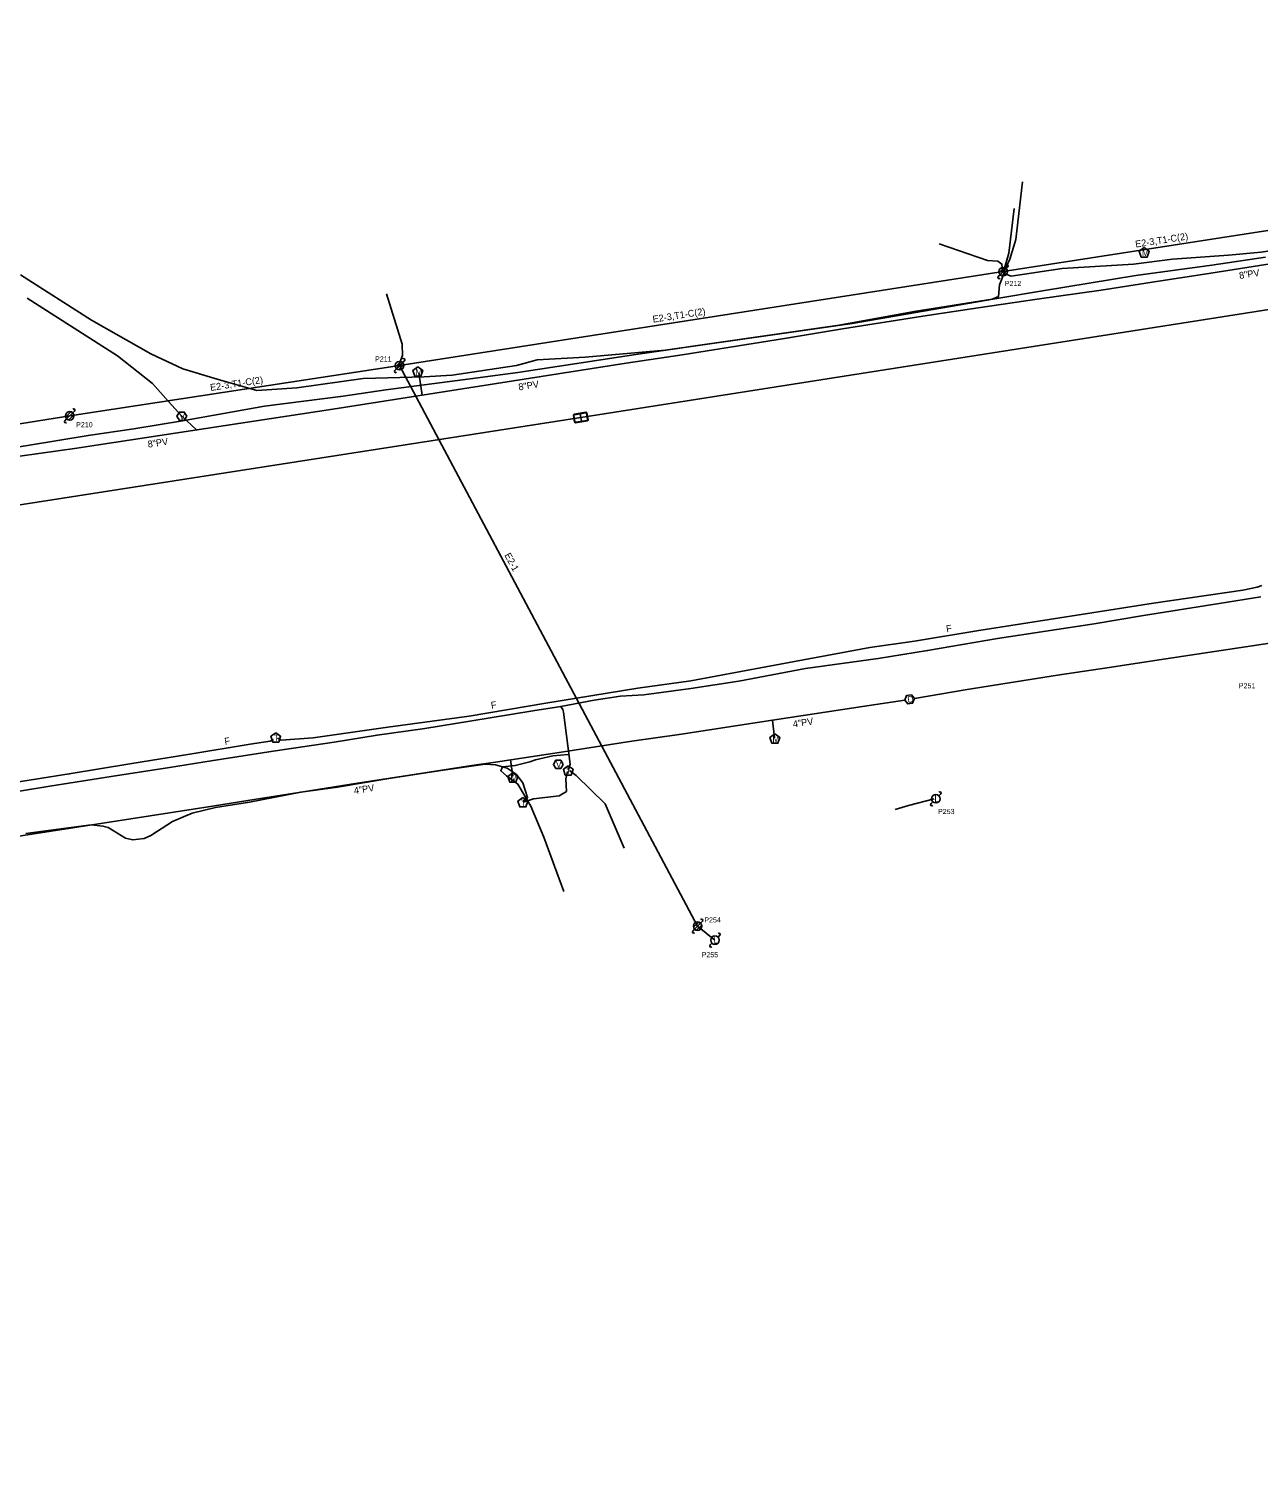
# Model space of a CAD drawing. Extents: x 1614474 to 1865144, y 1098877 to 1212550.
# Drawn here: x 1774346 to 1775065, y 1179234 to 1180084 of the extents above; entities that cross this region are included whole.
import ezdxf

# ---------------------------------------------------------------- set-up
doc = ezdxf.new("R2010")
doc.units = 0
for name, color, linetype in [('BFUSER_DUCTENCLOSURE', 7, 'Continuous'), ('BFUSER_FIBERSPAN', 7, 'Continuous'), ('RD_EX_SU_Elec', 7, 'Continuous'), ('RD_EX_SU_H2O', 7, 'Continuous'), ('RD_EX_SU_Ovhd', 7, 'Continuous'), ('RD_EX_SU_Pole', 7, 'Continuous'), ('RD_EX_SU_Telecom', 7, 'Continuous'), ('RD_EX_SU_TX_H2O', 7, 'Continuous'), ('RD_EX_SU_TX_Pole', 7, 'Continuous'), ('RD_EX_SU_TX_Telecom', 7, 'Continuous')]:
    doc.layers.add(name, color=color, linetype=linetype)

# ---------------------------------------------------------------- blocks, each defined once
blk = doc.blocks.new('SUE_WV')
at = {"layer": 'RD_EX_SU_H2O'}
blk.add_lwpolyline([(2.89, 0), (1.44, 2.5), (-1.44, 2.5), (-2.89, 0), (-1.44, -2.5), (1.44, -2.5)], close=True, dxfattribs=at)
blk.add_text('V', height=3.75, dxfattribs=at).set_placement((-1.43, -1.88))
blk = doc.blocks.new('SUE_TPP')
at = {"layer": 'RD_EX_SU_Telecom'}
blk.add_lwpolyline([(0, 3), (-2.85, 0.93), (-1.76, -2.43), (1.76, -2.43), (2.85, 0.93)], close=True, dxfattribs=at)
blk.add_text('T', height=3.75, dxfattribs=at).set_placement((-1.25, -1.88))
blk = doc.blocks.new('SUE_WM')
at = {"layer": 'RD_EX_SU_H2O'}
blk.add_lwpolyline([(0, 3.05), (-2.9, 0.94), (-1.79, -2.47), (1.79, -2.47), (2.9, 0.94)], close=True, dxfattribs=at)
blk.add_text('M', height=3.75, dxfattribs=at).set_placement((-1.43, -1.88))

msp = doc.modelspace()

# ---------------------------------------------------------------- linework, layer by layer
at = {"layer": 'BFUSER_DUCTENCLOSURE'}
msp.add_line((1774668.33, 1179858.97), (1774669.09, 1179854.53), dxfattribs=at)
for points in [[(1774665.1, 1179854.11), (1774664.43, 1179858.05)], [(1774665.31, 1179854.29), (1774664.68, 1179857.94)], [(1774664.84, 1179858.63), (1774671.74, 1179859.81)], [(1774665.01, 1179858.41), (1774671.65, 1179859.54)], [(1774672.58, 1179854.88), (1774665.68, 1179853.7)], [(1774665.77, 1179853.96), (1774672.41, 1179855.1)], [(1774672.11, 1179859.22), (1774672.73, 1179855.56)], [(1774672.31, 1179859.4), (1774672.99, 1179855.46)]]:
    msp.add_lwpolyline(points, dxfattribs=at)
for centre, radius, start, end in [((1774664.92, 1179858.13), 0.5, 99.71434, 189.71434), ((1774665.08, 1179858.01), 0.4, 99.71434, 189.71434), ((1774665.7, 1179854.36), 0.4, 189.71434, 279.71434), ((1774671.72, 1179859.15), 0.4, 9.71434, 99.71434), ((1774671.82, 1179859.31), 0.5, 9.71434, 99.71434), ((1774672.34, 1179855.49), 0.4, 279.71434, 9.71434), ((1774672.5, 1179855.37), 0.5, 279.71434, 9.71434), ((1774665.6, 1179854.19), 0.5, 189.71434, 279.71434)]:
    msp.add_arc(centre, radius, start, end, dxfattribs=at)
at = {"layer": 'BFUSER_FIBERSPAN'}
msp.add_lwpolyline([(1772266.13, 1179233.73), (1772993.33, 1179552.36), (1773074.83, 1179562.18), (1773346.25, 1179631.55), (1773610.67, 1179692.14), (1774668.73, 1179856.77), (1776115.67, 1180083.91)], dxfattribs=at)
at = {"layer": 'RD_EX_SU_Elec'}
for points in [[(1774916.25, 1179942.7), (1774919.1, 1179952.84), (1774922.26, 1179978.94)], [(1774555.08, 1179929.09), (1774564.29, 1179899.72), (1774564.41, 1179893.09), (1774561.67, 1179885.87)], [(1774852.52, 1179627.55), (1774860.33, 1179629.86), (1774875.4, 1179633.84)]]:
    msp.add_lwpolyline(points, dxfattribs=at)
at = {"layer": 'RD_EX_SU_H2O'}
for p, q in [((1774573.94, 1179882.85), (1774575.99, 1179869.76)), ((1774782.06, 1179669.44), (1774780.83, 1179679.7)), ((1774629.01, 1179647.06), (1774627.54, 1179656.49))]:
    msp.add_line(p, q, dxfattribs=at)
for points in [[(1774386.57, 1179840.75), (1774523.66, 1179861.56), (1774695.31, 1179888.47), (1774727.98, 1179893.39), (1774787.79, 1179902.93), (1774821.83, 1179908.67), (1774868.74, 1179915.98), (1774901.09, 1179920.97), (1774935.63, 1179925.97), (1774973.03, 1179931.27), (1775005.49, 1179936.37), (1775033.48, 1179940.52), (1775079.31, 1179947.86)], [(1774344.93, 1179926.6), (1774397.84, 1179892.85), (1774418.28, 1179876.72), (1774427.52, 1179866.21), (1774435.39, 1179857.45), (1774444.06, 1179849.47)], [(1774340.65, 1179834.22), (1774374.01, 1179838.85), (1774386.57, 1179840.75)], [(1774863.89, 1179692.35), (1774894.76, 1179697.63), (1774947.51, 1179706.13), (1774977.79, 1179710.67), (1775010.86, 1179715.58), (1775118.28, 1179731.85)], [(1774780.83, 1179679.7), (1774798.85, 1179682.43), (1774833.58, 1179687.75), (1774858.18, 1179691.48)], [(1774726.3, 1179671.45), (1774780.83, 1179679.7)], [(1774658.71, 1179661.33), (1774698.65, 1179667.53), (1774726.3, 1179671.45)], [(1774618.77, 1179655.13), (1774658.71, 1179661.33)], [(1774453.3, 1179629.47), (1774464.17, 1179631.16), (1774477.78, 1179633.32), (1774506.4, 1179637.81), (1774538.15, 1179642.86), (1774571.3, 1179648.03), (1774604.98, 1179653.23), (1774618.77, 1179655.13)], [(1774405.62, 1179622.06), (1774453.3, 1179629.47)], [(1774192.53, 1179589.02), (1774326.1, 1179609.7), (1774405.62, 1179622.06)]]:
    msp.add_lwpolyline(points, dxfattribs=at)
msp.add_lwpolyline([(1774863.89, 1179692.35), (1774862.08, 1179694.6), (1774859.23, 1179694.17), (1774858.18, 1179691.48), (1774859.98, 1179689.23), (1774862.83, 1179689.66)], close=True, dxfattribs=at)
at = {"layer": 'RD_EX_SU_Ovhd'}
for p, q in [((1774915.73, 1179942.05), (1775173.97, 1179982.14)), ((1774562.77, 1179887.09), (1774915.73, 1179942.05)), ((1774369.81, 1179857.7), (1774562.77, 1179887.09)), ((1774562.77, 1179887.09), (1774737.07, 1179559.31)), ((1774171.34, 1179826.61), (1774369.81, 1179857.7)), ((1774737.07, 1179559.31), (1774747.23, 1179551.14))]:
    msp.add_line(p, q, dxfattribs=at)
at = {"layer": 'RD_EX_SU_Pole'}
for p, q in [((1774912.9, 1179939.22), (1774913.96, 1179940.28)), ((1774913.32, 1179941.4), (1774916.38, 1179944.46)), ((1774913.96, 1179940.28), (1774917.5, 1179943.81)), ((1774915.08, 1179939.63), (1774918.15, 1179942.69)), ((1774917.5, 1179943.81), (1774918.56, 1179944.87)), ((1774560.35, 1179886.44), (1774563.42, 1179889.5)), ((1774561, 1179885.32), (1774564.54, 1179888.86)), ((1774564.54, 1179888.86), (1774565.6, 1179889.92)), ((1774559.94, 1179884.26), (1774561, 1179885.32)), ((1774562.12, 1179884.67), (1774565.18, 1179887.74)), ((1774366.98, 1179854.87), (1774368.04, 1179855.93)), ((1774367.39, 1179857.05), (1774370.45, 1179860.12)), ((1774368.04, 1179855.93), (1774371.57, 1179859.47)), ((1774369.16, 1179855.29), (1774372.22, 1179858.35)), ((1774371.57, 1179859.47), (1774372.64, 1179860.53)), ((1774878.18, 1179635.61), (1774879.24, 1179636.67)), ((1774873.59, 1179631.01), (1774874.65, 1179632.07)), ((1774734.25, 1179556.48), (1774735.31, 1179557.54)), ((1774734.66, 1179558.66), (1774737.72, 1179561.73)), ((1774735.31, 1179557.54), (1774738.84, 1179561.08)), ((1774736.43, 1179556.9), (1774739.49, 1179559.96)), ((1774738.84, 1179561.08), (1774739.9, 1179562.14)), ((1774744.4, 1179548.31), (1774745.46, 1179549.37)), ((1774749, 1179552.91), (1774750.06, 1179553.97))]:
    msp.add_line(p, q, dxfattribs=at)
for centre in [(1774915.73, 1179942.05), (1774562.77, 1179887.09), (1774369.81, 1179857.7), (1774876.41, 1179633.84), (1774737.07, 1179559.31), (1774747.23, 1179551.14)]:
    msp.add_circle(centre, 2.5, dxfattribs=at)
for centre, start, end in [((1774918.03, 1179945.4), 315, 135), ((1774913.43, 1179938.69), 135, 315), ((1774565.07, 1179890.45), 315, 135), ((1774560.47, 1179883.73), 135, 315), ((1774367.51, 1179854.34), 135, 315), ((1774372.1, 1179861.06), 315, 135), ((1774878.71, 1179637.2), 315, 135), ((1774874.12, 1179630.48), 135, 315), ((1774739.37, 1179562.67), 315, 135), ((1774734.78, 1179555.95), 135, 315), ((1774744.93, 1179547.78), 135, 315), ((1774749.53, 1179554.5), 315, 135)]:
    msp.add_arc(centre, 0.75, start, end, dxfattribs=at)
at = {"layer": 'RD_EX_SU_Telecom'}
for points in [[(1774916.38, 1179941.03), (1774920.42, 1179939.36), (1774950.29, 1179943.85), (1774992.02, 1179946.41), (1775014.85, 1179949.27), (1775047.5, 1179951.68), (1775066.74, 1179953.51), (1775123.7, 1179962.38), (1775145.09, 1179965.59), (1775170.3, 1179968.62), (1775201.86, 1179975.29), (1775224.39, 1179978.23), (1775259.05, 1179984.49), (1775284.41, 1179989.29), (1775327.61, 1179996.37), (1775362.32, 1180003.4), (1775379.35, 1180007.42), (1775383.77, 1180009.8), (1775387.12, 1180013.27)], [(1774916.23, 1179942.18), (1774919.75, 1179949.43), (1774923.28, 1179960.9), (1774927.12, 1179994.59)], [(1774878.31, 1179958.36), (1774906.57, 1179948.59), (1774912.58, 1179948.25), (1774915.01, 1179946.48), (1774915.43, 1179942.56)], [(1774435.74, 1179854.84), (1774483.67, 1179863.32), (1774529.75, 1179869.23), (1774554.79, 1179873.02), (1774604.11, 1179879.42), (1774631.95, 1179883.15), (1774703.48, 1179893.93), (1774755.23, 1179901.37), (1774827.43, 1179911.81), (1774910.96, 1179926.22), (1774938.82, 1179930.9), (1774993.33, 1179939.9), (1775037.74, 1179945.93), (1775069.26, 1179950.59)], [(1774340.99, 1179940.26), (1774382.62, 1179913.61), (1774417.31, 1179893.92), (1774436.08, 1179885.26), (1774456.05, 1179879.25), (1774479.3, 1179872.58), (1774502.65, 1179874.1), (1774541.39, 1179879.58), (1774577.11, 1179880.52), (1774593.47, 1179881.56), (1774631.18, 1179887.27), (1774643.23, 1179890.49), (1774671.27, 1179892.14), (1774718.13, 1179896.08), (1774776.31, 1179904.43), (1774819.81, 1179910.79), (1774863.67, 1179918.78), (1774909.36, 1179926), (1774913.01, 1179927.52), (1774913.67, 1179934.38), (1774916.52, 1179941.77)], [(1774172.04, 1179827.21), (1774179.79, 1179817.75), (1774181.31, 1179816.34), (1774184.57, 1179816.38), (1774196.78, 1179818.34), (1774221.01, 1179821.82), (1774246.55, 1179825.53), (1774273.46, 1179829.39), (1774311.87, 1179835.21), (1774345.11, 1179840.4), (1774380.61, 1179846.19), (1774407.39, 1179850.22), (1774435.74, 1179854.84)], [(1774491.43, 1179669.27), (1774493.51, 1179668.05), (1774512.21, 1179669.38), (1774555.82, 1179675.6), (1774603.37, 1179682.19), (1774648.25, 1179689.7), (1774702.14, 1179698.58), (1774733.03, 1179702.79), (1774777.05, 1179710.91), (1774837.88, 1179722.22), (1774863.84, 1179726.03), (1774901.59, 1179732.2), (1774961.49, 1179741.64), (1775003.61, 1179748.24), (1775055.87, 1179755.76), (1775064.29, 1179757.64), (1775067.09, 1179758.58)], [(1774661.45, 1179650.62), (1774662.47, 1179654.14), (1774661.1, 1179664.73), (1774658.65, 1179684.5), (1774658.29, 1179685.94), (1774657.04, 1179687.78), (1774676.55, 1179691.39), (1774692.02, 1179693.88), (1774705.62, 1179694.55), (1774733.01, 1179698.27), (1774761.23, 1179702.67), (1774800.26, 1179709.9), (1774842.67, 1179715.91), (1774871.59, 1179720.5), (1774912.48, 1179727.45), (1774968.92, 1179736.16), (1774997.91, 1179740.95), (1775042.08, 1179747.91), (1775066.5, 1179751.84)], [(1774488.83, 1179661.59), (1774524.41, 1179666.82), (1774549.59, 1179671.05), (1774577.5, 1179674.99), (1774603.78, 1179679.17), (1774640.76, 1179685.21), (1774657.04, 1179687.78)], [(1774333.9, 1179642.83), (1774369.52, 1179648.32), (1774404.9, 1179654.24), (1774440.15, 1179659.96), (1774475.43, 1179665.74), (1774487.06, 1179667.4), (1774489, 1179668.4)], [(1774116.37, 1179610.42), (1774117.08, 1179606.32), (1774117.49, 1179603.31), (1774150.39, 1179608.77), (1774193.48, 1179615.14), (1774217.19, 1179619.77), (1774240.88, 1179622.74), (1774276.24, 1179628.64), (1774298.79, 1179633.56), (1774322.6, 1179635.43), (1774358.12, 1179641.25), (1774394.1, 1179646.89), (1774428.11, 1179652.14), (1774452.57, 1179656.07), (1774488.83, 1179661.59)], [(1774661.32, 1179659.65), (1774652.43, 1179658.94), (1774642.2, 1179656.58), (1774638.89, 1179655.33), (1774630.27, 1179653.36), (1774623.04, 1179652.41), (1774621.9, 1179650.21), (1774625.21, 1179647.26), (1774631.98, 1179642.36), (1774639.6, 1179629.49), (1774647.12, 1179611.32), (1774658.75, 1179579.61)], [(1774344.09, 1179613.57), (1774382.42, 1179618.55), (1774389.29, 1179617.85), (1774392.25, 1179616.94), (1774402.4, 1179610.81), (1774406.72, 1179609.75), (1774413.31, 1179610.57), (1774417.35, 1179612.31), (1774429.96, 1179620.45), (1774441.48, 1179625.34), (1774455.12, 1179628.66), (1774474.99, 1179631.91), (1774504.95, 1179637.69), (1774526.36, 1179640.6), (1774556.43, 1179645.68), (1774588.27, 1179650.45), (1774612.78, 1179654.01), (1774618.8, 1179653.69), (1774625.67, 1179651.62), (1774630.94, 1179648.22), (1774634.8, 1179643.09), (1774637.62, 1179634.55), (1774637.02, 1179633.37), (1774634.8, 1179631.94)], [(1774662.08, 1179650.27), (1774665.96, 1179647.44), (1774683.04, 1179630.9), (1774694.19, 1179604.83)], [(1774635.04, 1179631.8), (1774641.15, 1179633.76), (1774656.1, 1179635.46), (1774660.48, 1179638.1), (1774659.96, 1179645.48), (1774660.93, 1179649.67)]]:
    msp.add_lwpolyline(points, dxfattribs=at)

# ---------------------------------------------------------------- block references
at = {"layer": 'RD_EX_SU_H2O'}
for name, p in [('SUE_WM', (1774998.3, 1179953.04)), ('SUE_WM', (1774573.37, 1179883.39)), ('SUE_WV', (1774435.39, 1179857.45)), ('SUE_WM', (1774782.27, 1179668.76)), ('SUE_WV', (1774655.61, 1179653.94)), ('SUE_WM', (1774629.03, 1179645.94))]:
    msp.add_blockref(name, p, dxfattribs=at)
at = {"layer": 'RD_EX_SU_Telecom'}
for p in [(1774490.35, 1179669.43), (1774661.39, 1179650.1), (1774634.84, 1179631.5)]:
    msp.add_blockref('SUE_TPP', p, dxfattribs=at)

# ---------------------------------------------------------------- texts
at = {"layer": 'RD_EX_SU_H2O'}
msp.add_text('D', height=3.75, rotation=8.63018, dxfattribs=at).set_placement((1774860.07, 1179689.87))
at = {"layer": 'RD_EX_SU_Ovhd'}
for s, rotation, p in [('E2-3,T1-C(2)', 8.82447, (1774993.36, 1179956.12)), ('E2-3,T1-C(2)', 8.85013, (1774711.06, 1179912.2)), ('E2-3,T1-C(2)', 8.65934, (1774452.27, 1179872.28)), ('E2-1', 298.00331, (1774623.94, 1179776.32))]:
    msp.add_text(s, height=4, rotation=rotation, dxfattribs=at).set_placement(p)
at = {"layer": 'RD_EX_SU_Pole'}
for p in [(1774875.55, 1179631.84), (1774746.37, 1179549.14)]:
    msp.add_text('L', height=4, dxfattribs=at).set_placement(p)
at = {"layer": 'RD_EX_SU_TX_H2O'}
for s, rotation, p in [('8"PV', 9.10403, (1775054.11, 1179937.75)), ('8"PV', 8.90979, (1774632.61, 1179872.56)), ('8"PV', 8.63102, (1774415.73, 1179839.11)), ('4"PV', 8.71325, (1774793.09, 1179675.48)), ('4"PV', 8.8588, (1774536.33, 1179636.51))]:
    msp.add_text(s, height=4, rotation=rotation, dxfattribs=at).set_placement(p)
at = {"layer": 'RD_EX_SU_TX_Pole'}
for s, p in [('P212', (1774916.7, 1179933.64)), ('P211', (1774548.42, 1179889.49)), ('P210', (1774373.56, 1179851.07)), ('P251', (1775053.61, 1179698.39)), ('P253', (1774877.66, 1179624.89)), ('P254', (1774740.97, 1179561.5)), ('P255', (1774739.43, 1179541.14))]:
    msp.add_text(s, height=3, dxfattribs=at).set_placement(p)
at = {"layer": 'RD_EX_SU_TX_Telecom'}
for rotation, p in [(9.27517, (1774882.76, 1179731.15)), (9.49836, (1774616.51, 1179686.42)), (9.29618, (1774460.66, 1179665.35))]:
    msp.add_text('F', height=4, rotation=rotation, dxfattribs=at).set_placement(p)

doc.saveas('drawing.dxf')
